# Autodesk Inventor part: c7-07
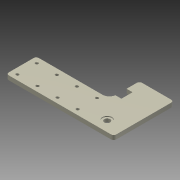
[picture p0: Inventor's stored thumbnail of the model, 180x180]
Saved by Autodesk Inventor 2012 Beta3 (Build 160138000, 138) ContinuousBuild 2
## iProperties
Created: 2010-12
Part Number: c7-07
Material: Steel
Document SubType Name: Modeling
Designer: Beta-8540w
Mass: 1769.34 g
Surface Area: 558.866 cm^2
Volume: 225.394 cm^3
Density: 7.85 g/cm^3
Author: Beta-8540w
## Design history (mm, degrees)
sketch "Sketch1"
  geometry: L1 (0, 0)-(250, 0); L2 (250, 0)-(250, 70); L3 (250, 70)-(0, 70); L4 (0, 70)-(0, 0); L5 (250, 70)-(170, 70); L6 (170, 70)-(170, 140); L7 (170, 140)-(250, 140); L8 (250, 140)-(250, 70)
  constraints: 16 end point, 4 parallel, 2 horizontal, 2 perpendicular
  dimensions: "d0" = 250 distance of L3.end L2.end; "d1" = 70 distance of L2.end L1.end; "d2" = 80 distance of L6.end L7.end; "d3" = 70 distance of L5.end L6.end
extrude "Extrusion1" new body sketch "Sketch1" distance "d4" = 10; taper "d5" = 0 deg
sketch "Sketch4"
  geometry: L1 (250, 140)-(170, 140) reference; L2 (170, 140)-(170, 70) reference; L3 (170, 84)-(184, 84); L4 (184, 84)-(184, 110); L5 (184, 110)-(170, 110); L6 (170, 110)-(170, 84)
  constraints: 8 end point, 2 parallel, 1 horizontal, 1 perpendicular, 1 point on line
  dimensions: "d41" = 14 distance of L5.end L4.end; "d42" = 26 distance of L4.end L3.end; "d43" = 30 distance between parallel lines of L1 L5
extrude "Extrusion2" cut sketch "Sketch4" stored distance "d44" = 10; taper "d45" = 0 deg
sketch "Sketch2"
  geometry: L1 (0, 70)-(0, 0) reference; L2 (14, 12.5)-(154, 12.5); L3 (154, 12.5)-(154, 57.5); L4 (154, 57.5)-(14, 57.5); L5 (14, 57.5)-(14, 12.5); L6 (60.667, 57.5)-(60.667, 12.5); L7 (107.333, 57.5)-(107.333, 12.5); 2 further points
  constraints: 12 end point, 4 point on line, 3 perpendicular, 2 midpoint, 2 parallel, 1 horizontal, 1 horizontal alignment
  dimensions: "d6" = 140 distance of L4.end L3.end; "d7" = 45 distance of L3.end L2.end; "d8" = 46.66667 distance between parallel lines of L6 L5 (= 0.333333 x d6); "d9" = 46.66667 distance between parallel lines of L7 L6 (= d8); "d10" = 14 distance between parallel lines of L1 L5
hole "Hole1" sketch "Sketch2" at (14, 12.5), (154, 57.5), (154, 12.5), (14, 57.5), (60.667, 57.5), (60.667, 12.5), (107.333, 57.5), (107.333, 12.5) diameter "d11" = 6.6; stored, may be unused: countersink angle "d15" = 90 deg, drill point angle "d17" = 118 deg; dims "d12" = 6, "d13" = 4, "d14" = 90, "d16" = 8
hole "Hole3" diameter "d52" = 3.242; stored, may be unused: countersink angle "d56" = 90 deg, drill point angle "d58" = 118 deg; dims "d50" = 43, "d51" = 5, "d53" = 8, "d54" = 4, "d55" = 2, "d57" = 10
fillet "Fillet1" dims "d39" = 6, "d46" = 1
fillet "Fillet2" dims "d40" = 16
chamfer "Chamfer1" distance "d47" = 0.5; stored, may be unused: second distance "d48" = 2, angle "d49" = 45 deg
chamfer "Chamfer2" distance "d59" = 0.5; stored, may be unused: second distance "d60" = 2, angle "d61" = 45 deg
body "Solid1"
hole "Hole2" diameter "d32" = 13.492; stored, may be unused: countersink angle "d36" = 90 deg, drill point angle "d38" = 118 deg; dims "d30" = 40, "d31" = 25, "d33" = 6, "d34" = 22.225, "d35" = 2, "d37" = 8
